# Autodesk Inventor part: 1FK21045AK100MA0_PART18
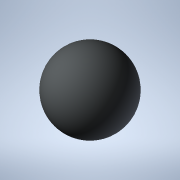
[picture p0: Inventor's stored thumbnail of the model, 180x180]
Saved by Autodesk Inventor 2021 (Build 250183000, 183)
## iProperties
Created: 2025-04
Part Number: 1FK21045AK100MA0_PART18
Material: Generic
Catalog Web Link: www.3dfindit.com
Description: -Servo synchronous motor
Document SubType Name: Modeling
Designer: psAdmin
Mass: 0.137258 g
Surface Area: 1.2868 cm^2
Volume: 0.137258 cm^3
Density: 1 g/cm^3
Appearance: PSOLRGB-212-217-219
Category: PARTsolutions
Title: 1FK21045AK100MA0_PART18
Author: Cadenas PARTsolutions
Comments: Servo synchronous motor
Sending System: PARTsolutions
Preprocessor: ST-DEVELOPER v19.3
PSOL_IDENT_0: {$CADENAS_DATA/23d-libs/siemens_ag/_cat_/e0/5f/1fk21045ak100ma0.prj},216 {VTYP=3D},{NB=1FK21045AK100
PSOL_IDENT_1: MA0_PART18},{LINA=1FK21045AK100MA0_PART18},{NN=1FK21045AK100MA0_PART18},{NOPRJ=TRUE},{DATE=19.08.202
PSOL_IDENT_2: 5 14:01:03},{GEOMDATE=30.07.2025 02:01:57},{VERSION=},{LINEID=10},{WBVAR=},{WBNUMERIC=}  {NB=1FK2104
PSOL_IDENT_3: 5AK100MA0_PART18},{LINA=1FK21045AK100MA0_PART18},{KT=DUMMY},{PREVIEW=../../../_pool_/0f/2c/p_d211_xx
PSOL_IDENT_4: _00438j.png},{DESCSHORT=SIMOTICS S-1FK2 HD, SINAMICS S210 3AC 400V-480V, 1.7 Nm, 6000 rpm},{DESCLONG=
PSOL_IDENT_5: SIMOTICS S-1FK2 HD servo motor M0=2.4 Nm; PN = 1.07 kW at nN=6000 rpm (380-480 V); PN = 0.75 kW at n
PSOL_IDENT_6: N=3000 rpm (200-240 V); with holding brake; degree of protection IP64; cylindrical shaft D19x40mm; a
PSOL_IDENT_7: bsolute encoder 22-bit + 12-bit multiturn (encoder AM22DQC); with OCC interface; plug size M17, rota
PSOL_IDENT_8: table; SIMOTICS S-1FK2 servomotorfor a wide range of uses in industrial environments. SIMOTICS S‑1FK
PSOL_IDENT_9: 2 servomotors are compact synchronous motors with a high dynamic performance that set themselves apa
PSOL_IDENT_10: rt as a result of their high power density, degree of protection and overload capability. The motors
PSOL_IDENT_11: are available in two variants: as High Dynamic variant (highest dynamic performance as a result of
PSOL_IDENT_12: the low intrinsic moment of inertia for applications demanding a high dynamic performance with low m
PSOL_IDENT_13: oved masses) - and as Compact variant (precise and stable closed-loop control for medium up to large
PSOL_IDENT_14: moved masses as a result of a medium intrinsic moment of inertia). SIMOTICSS‑1FK2 servomotors fully
PSOL_IDENT_15: exploit their strengths in a system with the SINAMICSS210 frequency converter and simple connection
PSOL_IDENT_16: using the one cable connection (OCC). Advantages include the short control and positioning times, f
PSOL_IDENT_17: ast and precise correction of disturbing quantities as well as stable control with a high dynamic pe
PSOL_IDENT_18: rformance. The servo motors can be configured to address a wide range of requirements. For example w
PSOL_IDENT_19: ith and without holding brake, IP64 or IP65 degree of protection, singleturn or multiturn absolute e
PSOL_IDENT_20: ncoders - to name just a few. Further, the servomotors are available in different shaft heights exte
PSOL_IDENT_21: nding from 20 to 100. A shaft sealing ring is available to achieve an IP65 degree of protection and
PSOL_IDENT_22: for subsequent mounting at the motor or as spare part. SIMOTICS - the optimum motor for each and eve
PSOL_IDENT_23: ry motion control application.},{INTNO=804766807114},{SUPPLIERALTNO=1FK2104-5AK10-0MA0},{MANUID=1FK2
PSOL_IDENT_24: 1045AK100MA0},{MANUNAME=Siemens},{MANUTYPEDESC=Synchronous motor 1FK2-HD 2,39 Nm},{AAU732=SIMOTICS},
PSOL_IDENT_25: {AAO057=S-1FK2},{AAU734=SIMOTICS S-1FK2 HD servo motor M0=2.4 Nm; PN = 1.07 kW at nN=6000 rpm (380-4
PSOL_IDENT_26: 80 V); PN = 0.75 kW at nN=3000 rpm (200-240 V); with holding brake; degree of protection IP64; cylin
PSOL_IDENT_27: drical shaft D19x40mm; absolute encoder 22-bit + 12-bit multiturn (encoder AM22DQC); with OCC interf
PSOL_IDENT_28: ace; plug size M17, rotatable;},{AAW338=Synchronous motor 1FK2-HD 2,39 Nm},{AAO742=SIMOTICS},{AAO663=
PSOL_IDENT_29: 4042948691236},{NOCUPEROU=1},{PRICEQUANTITY=1},{QUANTITYMIN=1},{QUANTITYINT=1},{CTN=85015100},{COO=D
PSOL_IDENT_30: E},{AAO676=1FK2104-5AK10-0MA0},{AAO677=Siemens AG},{ORDERUNIT=C62},{CONTENTUNIT=C62}
NB: 1FK21045AK100MA0_PART18
NT: Servo synchronous motor
NBSYN: $MANUID._PART18
LINA: 1FK21045AK100MA0_PART18
CATALOG: SIEMENS
PREVIEW: ../../../_pool_/0f/2c/p_d211_xx_00438j.png
DESCSHORT: SIMOTICS S-1FK2 HD, SINAMICS S210 3AC 400V-480V, 1.7 Nm, 6000 rpm
DESCLONG: SIMOTICS S-1FK2 HD servo motor M0=2.4 Nm; PN = 1.07 kW at nN=6000 rpm (380-480 V); PN = 0.75 kW at nN=3000 rpm (200-240 V); with holding brake; degree of protec
INTNO: 804766807114
SUPPLIERALTNO: 1FK2104-5AK10-0MA0
MANUID: 1FK21045AK100MA0
MANUNAME: Siemens
MANUTYPEDESC: Synchronous motor 1FK2-HD 2,39 Nm
AAU732: SIMOTICS
AAO057: S-1FK2
AAU734: SIMOTICS S-1FK2 HD servo motor M0=2.4 Nm; PN = 1.07 kW at nN=6000 rpm (380-480 V); PN = 0.75 kW at nN=3000 rpm (200-240 V); with holding brake; degree of protec
AAW338: Synchronous motor 1FK2-HD 2,39 Nm
AAO742: SIMOTICS
AAO663: 4042948691236.0
NOCUPEROU: 1
PRICEQUANTITY: 1
QUANTITYMIN: 1
QUANTITYINT: 1
CTN: 85015100
COO: DE
ARTICLENO: 1FK21045AK100MA0_PART18
BOMINFO: 1FK21045AK100MA0_PART18
CREATOR: CADENAS GmbH
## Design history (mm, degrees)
feature "2025_04_17_15_45_15_0090"
body "Solid1"
